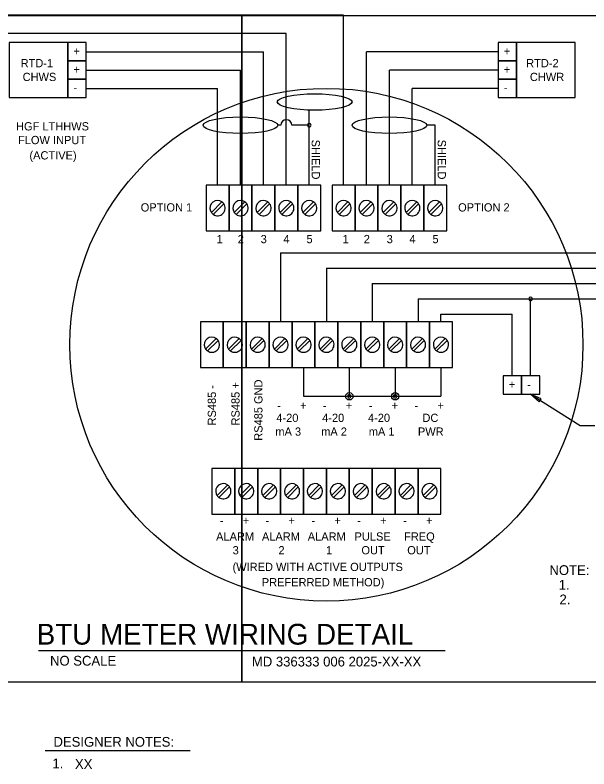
# Model space of a CAD drawing. Extents: x 10010.3 to 10109.1, y 10088 to 10139.5.
# Drawn here: x 10043.9 to 10083.1, y 10088 to 10139.5 of the extents above; entities that cross this region are included whole.
import ezdxf

# ---------------------------------------------------------------- set-up
doc = ezdxf.new("R2010")
doc.units = 0
for name, color, linetype in [('Default', 7, 'Continuous'), ('G-DETL-GRID', 7, 'Continuous'), ('G-DETL-LINE', 7, 'Continuous')]:
    doc.layers.add(name, color=color, linetype=linetype)

# ---------------------------------------------------------------- blocks, each defined once
blk = doc.blocks.new('leadarrow-a')
blk.add_lwpolyline([(0.00814, -0.00136), (0.00814, 0.00136), (0, 0)], close=True)

msp = doc.modelspace()

# ---------------------------------------------------------------- linework, layer by layer
for p, q in [((10079.106, 10113.625), (10082.496, 10111.49)), ((10082.496, 10111.49), (10083.487, 10111.49)), ((10045.538, 10096.133), (10073.277, 10096.133)), ((10046, 10089.309), (10055.886, 10089.309))]:
    msp.add_line(p, q)
at = {"layer": 'Default'}
for p, q in [((10058.055, 10126.754), (10057.331, 10126.029)), ((10057.46, 10125.9), (10058.184, 10126.625)), ((10059.618, 10126.754), (10058.893, 10126.029)), ((10059.022, 10125.9), (10059.747, 10126.625)), ((10061.18, 10126.754), (10060.456, 10126.029)), ((10060.585, 10125.9), (10061.309, 10126.625)), ((10062.743, 10126.754), (10062.018, 10126.029)), ((10062.147, 10125.9), (10062.872, 10126.625)), ((10064.305, 10126.754), (10063.581, 10126.029)), ((10063.71, 10125.9), (10064.434, 10126.625)), ((10066.649, 10126.754), (10065.925, 10126.029)), ((10066.053, 10125.9), (10066.778, 10126.625)), ((10068.212, 10126.754), (10067.487, 10126.029)), ((10067.616, 10125.9), (10068.341, 10126.625)), ((10069.774, 10126.754), (10069.05, 10126.029)), ((10069.178, 10125.9), (10069.903, 10126.625)), ((10071.337, 10126.754), (10070.612, 10126.029)), ((10070.741, 10125.9), (10071.466, 10126.625)), ((10072.899, 10126.754), (10072.175, 10126.029)), ((10072.303, 10125.9), (10073.028, 10126.625)), ((10079.106, 10114.875), (10079.106, 10120.126)), ((10072.992, 10118.563), (10072.992, 10119.078)), ((10072.992, 10119.078), (10077.856, 10119.078)), ((10077.856, 10114.875), (10077.856, 10119.078)), ((10057.665, 10117.427), (10056.94, 10116.702)), ((10057.069, 10116.574), (10057.794, 10117.298)), ((10059.227, 10117.427), (10058.503, 10116.702)), ((10058.632, 10116.574), (10059.356, 10117.298)), ((10060.79, 10117.427), (10060.065, 10116.702)), ((10060.194, 10116.574), (10060.919, 10117.298)), ((10062.352, 10117.427), (10061.628, 10116.702)), ((10061.757, 10116.574), (10062.481, 10117.298)), ((10063.915, 10117.427), (10063.19, 10116.702)), ((10063.319, 10116.574), (10064.044, 10117.298)), ((10065.477, 10117.427), (10064.753, 10116.702)), ((10064.882, 10116.574), (10065.606, 10117.298)), ((10067.04, 10117.427), (10066.315, 10116.702)), ((10066.444, 10116.574), (10067.169, 10117.298)), ((10068.602, 10117.427), (10067.878, 10116.702)), ((10068.007, 10116.574), (10068.731, 10117.298)), ((10070.165, 10117.427), (10069.44, 10116.702)), ((10069.569, 10116.574), (10070.294, 10117.298)), ((10071.727, 10117.427), (10071.003, 10116.702)), ((10071.132, 10116.574), (10071.856, 10117.298)), ((10073.29, 10117.427), (10072.565, 10116.702)), ((10072.694, 10116.574), (10073.419, 10117.298)), ((10063.617, 10115.438), (10063.617, 10113.481)), ((10066.742, 10115.438), (10066.742, 10113.481)), ((10069.867, 10115.438), (10069.867, 10113.481)), ((10072.992, 10115.438), (10072.992, 10113.481)), ((10063.617, 10113.481), (10066.742, 10113.481)), ((10066.742, 10113.481), (10069.867, 10113.481)), ((10069.867, 10113.481), (10072.992, 10113.481)), ((10058.446, 10107.427), (10057.722, 10106.702)), ((10057.85, 10106.574), (10058.575, 10107.298)), ((10060.009, 10107.427), (10059.284, 10106.702)), ((10059.413, 10106.574), (10060.137, 10107.298)), ((10061.571, 10107.427), (10060.847, 10106.702)), ((10060.975, 10106.574), (10061.7, 10107.298)), ((10063.134, 10107.427), (10062.409, 10106.702)), ((10062.538, 10106.574), (10063.262, 10107.298)), ((10064.696, 10107.427), (10063.972, 10106.702)), ((10064.1, 10106.574), (10064.825, 10107.298)), ((10066.259, 10107.427), (10065.534, 10106.702)), ((10065.663, 10106.574), (10066.387, 10107.298)), ((10067.821, 10107.427), (10067.097, 10106.702)), ((10067.225, 10106.574), (10067.95, 10107.298)), ((10069.384, 10107.427), (10068.659, 10106.702)), ((10068.788, 10106.574), (10069.512, 10107.298)), ((10070.946, 10107.427), (10070.222, 10106.702)), ((10070.35, 10106.574), (10071.075, 10107.298)), ((10072.509, 10107.427), (10071.784, 10106.702)), ((10071.913, 10106.574), (10072.637, 10107.298))]:
    msp.add_line(p, q, dxfattribs=at)
for points in [[(10056.976, 10124.765), (10058.539, 10124.765), (10058.539, 10127.89), (10056.976, 10127.89), (10056.976, 10124.765)], [(10058.539, 10124.765), (10060.101, 10124.765), (10060.101, 10127.89), (10058.539, 10127.89), (10058.539, 10124.765)], [(10060.101, 10124.765), (10061.664, 10124.765), (10061.664, 10127.89), (10060.101, 10127.89), (10060.101, 10124.765)], [(10061.664, 10124.765), (10063.226, 10124.765), (10063.226, 10127.89), (10061.664, 10127.89), (10061.664, 10124.765)], [(10063.226, 10124.765), (10064.789, 10124.765), (10064.789, 10127.89), (10063.226, 10127.89), (10063.226, 10124.765)], [(10065.57, 10124.765), (10067.133, 10124.765), (10067.133, 10127.89), (10065.57, 10127.89), (10065.57, 10124.765)], [(10067.133, 10124.765), (10068.695, 10124.765), (10068.695, 10127.89), (10067.133, 10127.89), (10067.133, 10124.765)], [(10068.695, 10124.765), (10070.258, 10124.765), (10070.258, 10127.89), (10068.695, 10127.89), (10068.695, 10124.765)], [(10070.258, 10124.765), (10071.82, 10124.765), (10071.82, 10127.89), (10070.258, 10127.89), (10070.258, 10124.765)], [(10071.82, 10124.765), (10073.383, 10124.765), (10073.383, 10127.89), (10071.82, 10127.89), (10071.82, 10124.765)], [(10056.586, 10115.438), (10058.148, 10115.438), (10058.148, 10118.563), (10056.586, 10118.563), (10056.586, 10115.438)], [(10058.148, 10115.438), (10059.711, 10115.438), (10059.711, 10118.563), (10058.148, 10118.563), (10058.148, 10115.438)], [(10059.711, 10115.438), (10061.273, 10115.438), (10061.273, 10118.563), (10059.711, 10118.563), (10059.711, 10115.438)], [(10061.273, 10115.438), (10062.836, 10115.438), (10062.836, 10118.563), (10061.273, 10118.563), (10061.273, 10115.438)], [(10062.836, 10115.438), (10064.398, 10115.438), (10064.398, 10118.563), (10062.836, 10118.563), (10062.836, 10115.438)], [(10064.398, 10115.438), (10065.961, 10115.438), (10065.961, 10118.563), (10064.398, 10118.563), (10064.398, 10115.438)], [(10065.961, 10115.438), (10067.523, 10115.438), (10067.523, 10118.563), (10065.961, 10118.563), (10065.961, 10115.438)], [(10067.523, 10115.438), (10069.086, 10115.438), (10069.086, 10118.563), (10067.523, 10118.563), (10067.523, 10115.438)], [(10069.086, 10115.438), (10070.648, 10115.438), (10070.648, 10118.563), (10069.086, 10118.563), (10069.086, 10115.438)], [(10070.648, 10115.438), (10072.211, 10115.438), (10072.211, 10118.563), (10070.648, 10118.563), (10070.648, 10115.438)], [(10072.211, 10115.438), (10073.773, 10115.438), (10073.773, 10118.563), (10072.211, 10118.563), (10072.211, 10115.438)], [(10077.231, 10113.625), (10078.481, 10113.625), (10078.481, 10114.875), (10077.231, 10114.875), (10077.231, 10113.625)], [(10078.481, 10113.625), (10079.731, 10113.625), (10079.731, 10114.875), (10078.481, 10114.875), (10078.481, 10113.625)], [(10057.367, 10105.438), (10058.929, 10105.438), (10058.929, 10108.563), (10057.367, 10108.563), (10057.367, 10105.438)], [(10058.929, 10105.438), (10060.492, 10105.438), (10060.492, 10108.563), (10058.929, 10108.563), (10058.929, 10105.438)], [(10060.492, 10105.438), (10062.054, 10105.438), (10062.054, 10108.563), (10060.492, 10108.563), (10060.492, 10105.438)], [(10062.054, 10105.438), (10063.617, 10105.438), (10063.617, 10108.563), (10062.054, 10108.563), (10062.054, 10105.438)], [(10063.617, 10105.438), (10065.179, 10105.438), (10065.179, 10108.563), (10063.617, 10108.563), (10063.617, 10105.438)], [(10065.179, 10105.438), (10066.742, 10105.438), (10066.742, 10108.563), (10065.179, 10108.563), (10065.179, 10105.438)], [(10066.742, 10105.438), (10068.304, 10105.438), (10068.304, 10108.563), (10066.742, 10108.563), (10066.742, 10105.438)], [(10068.304, 10105.438), (10069.867, 10105.438), (10069.867, 10108.563), (10068.304, 10108.563), (10068.304, 10105.438)], [(10069.867, 10105.438), (10071.429, 10105.438), (10071.429, 10108.563), (10069.867, 10108.563), (10069.867, 10105.438)], [(10071.429, 10105.438), (10072.992, 10105.438), (10072.992, 10108.563), (10071.429, 10108.563), (10071.429, 10105.438)]]:
    msp.add_lwpolyline(points, dxfattribs=at)
for centre, radius in [((10065.179, 10117), 17.5), ((10066.742, 10113.481), 0.25), ((10069.867, 10113.481), 0.25)]:
    msp.add_circle(centre, radius, dxfattribs=at)
for centre, radius, start, end in [((10057.758, 10126.327), 0.52, 55.0787, 200.4873), ((10059.32, 10126.327), 0.52, 55.0787, 200.4873), ((10060.883, 10126.327), 0.52, 55.0787, 200.4873), ((10062.445, 10126.327), 0.52, 55.0787, 200.4873), ((10064.008, 10126.327), 0.52, 55.0787, 200.4873), ((10066.351, 10126.327), 0.52, 55.0787, 200.4873), ((10067.914, 10126.327), 0.52, 55.0787, 200.4873), ((10069.476, 10126.327), 0.52, 55.0787, 200.4873), ((10071.039, 10126.327), 0.52, 55.0787, 200.4873), ((10072.601, 10126.327), 0.52, 55.0787, 200.4873), ((10057.758, 10126.327), 0.52, 235.0787, 34.9213), ((10057.758, 10126.327), 0.52, 34.9213, 55.0787), ((10059.32, 10126.327), 0.52, 235.0787, 34.9213), ((10059.32, 10126.327), 0.52, 34.9213, 55.0787), ((10060.883, 10126.327), 0.52, 235.0787, 34.9213), ((10060.883, 10126.327), 0.52, 34.9213, 55.0787), ((10062.445, 10126.327), 0.52, 235.0787, 34.9213), ((10062.445, 10126.327), 0.52, 34.9213, 55.0787), ((10064.008, 10126.327), 0.52, 235.0787, 34.9213), ((10064.008, 10126.327), 0.52, 34.9213, 55.0787), ((10066.351, 10126.327), 0.52, 235.0787, 34.9213), ((10066.351, 10126.327), 0.52, 34.9213, 55.0787), ((10067.914, 10126.327), 0.52, 235.0787, 34.9213), ((10067.914, 10126.327), 0.52, 34.9213, 55.0787), ((10069.476, 10126.327), 0.52, 235.0787, 34.9213), ((10069.476, 10126.327), 0.52, 34.9213, 55.0787), ((10071.039, 10126.327), 0.52, 235.0787, 34.9213), ((10071.039, 10126.327), 0.52, 34.9213, 55.0787), ((10072.601, 10126.327), 0.52, 235.0787, 34.9213), ((10072.601, 10126.327), 0.52, 34.9213, 55.0787), ((10057.758, 10126.327), 0.52, 200.4873, 214.9213), ((10057.758, 10126.327), 0.52, 214.9213, 235.0787), ((10059.32, 10126.327), 0.52, 200.4873, 214.9213), ((10059.32, 10126.327), 0.52, 214.9213, 235.0787), ((10060.883, 10126.327), 0.52, 200.4873, 214.9213), ((10060.883, 10126.327), 0.52, 214.9213, 235.0787), ((10062.445, 10126.327), 0.52, 200.4873, 214.9213), ((10062.445, 10126.327), 0.52, 214.9213, 235.0787), ((10064.008, 10126.327), 0.52, 200.4873, 214.9213), ((10064.008, 10126.327), 0.52, 214.9213, 235.0787), ((10066.351, 10126.327), 0.52, 200.4873, 214.9213), ((10066.351, 10126.327), 0.52, 214.9213, 235.0787), ((10067.914, 10126.327), 0.52, 200.4873, 214.9213), ((10067.914, 10126.327), 0.52, 214.9213, 235.0787), ((10069.476, 10126.327), 0.52, 200.4873, 214.9213), ((10069.476, 10126.327), 0.52, 214.9213, 235.0787), ((10071.039, 10126.327), 0.52, 200.4873, 214.9213), ((10071.039, 10126.327), 0.52, 214.9213, 235.0787), ((10072.601, 10126.327), 0.52, 200.4873, 214.9213), ((10072.601, 10126.327), 0.52, 214.9213, 235.0787), ((10079.106, 10120.126), 0.125, 0, 180), ((10079.106, 10120.126), 0.125, 180, 0), ((10057.367, 10117), 0.52, 55.0787, 200.4873), ((10057.367, 10117), 0.52, 235.0787, 34.9213), ((10057.367, 10117), 0.52, 34.9213, 55.0787), ((10058.929, 10117), 0.52, 55.0787, 200.4873), ((10058.929, 10117), 0.52, 235.0787, 34.9213), ((10058.929, 10117), 0.52, 34.9213, 55.0787), ((10060.492, 10117), 0.52, 55.0787, 200.4873), ((10060.492, 10117), 0.52, 235.0787, 34.9213), ((10060.492, 10117), 0.52, 34.9213, 55.0787), ((10062.054, 10117), 0.52, 55.0787, 200.4873), ((10062.054, 10117), 0.52, 235.0787, 34.9213), ((10062.054, 10117), 0.52, 34.9213, 55.0787), ((10063.617, 10117), 0.52, 55.0787, 200.4873), ((10063.617, 10117), 0.52, 235.0787, 34.9213), ((10063.617, 10117), 0.52, 34.9213, 55.0787), ((10065.179, 10117), 0.52, 55.0787, 200.4873), ((10065.179, 10117), 0.52, 235.0787, 34.9213), ((10065.179, 10117), 0.52, 34.9213, 55.0787), ((10066.742, 10117), 0.52, 55.0787, 200.4873), ((10066.742, 10117), 0.52, 235.0787, 34.9213), ((10066.742, 10117), 0.52, 34.9213, 55.0787), ((10068.304, 10117), 0.52, 55.0787, 200.4873), ((10068.304, 10117), 0.52, 235.0787, 34.9213), ((10068.304, 10117), 0.52, 34.9213, 55.0787), ((10069.867, 10117), 0.52, 55.0787, 200.4873), ((10069.867, 10117), 0.52, 235.0787, 34.9213), ((10069.867, 10117), 0.52, 34.9213, 55.0787), ((10071.429, 10117), 0.52, 55.0787, 200.4873), ((10071.429, 10117), 0.52, 235.0787, 34.9213), ((10071.429, 10117), 0.52, 34.9213, 55.0787), ((10072.992, 10117), 0.52, 55.0787, 200.4873), ((10072.992, 10117), 0.52, 235.0787, 34.9213), ((10072.992, 10117), 0.52, 34.9213, 55.0787), ((10057.367, 10117), 0.52, 200.4873, 214.9213), ((10057.367, 10117), 0.52, 214.9213, 235.0787), ((10058.929, 10117), 0.52, 200.4873, 214.9213), ((10058.929, 10117), 0.52, 214.9213, 235.0787), ((10060.492, 10117), 0.52, 200.4873, 214.9213), ((10060.492, 10117), 0.52, 214.9213, 235.0787), ((10062.054, 10117), 0.52, 200.4873, 214.9213), ((10062.054, 10117), 0.52, 214.9213, 235.0787), ((10063.617, 10117), 0.52, 200.4873, 214.9213), ((10063.617, 10117), 0.52, 214.9213, 235.0787), ((10065.179, 10117), 0.52, 200.4873, 214.9213), ((10065.179, 10117), 0.52, 214.9213, 235.0787), ((10066.742, 10117), 0.52, 200.4873, 214.9213), ((10066.742, 10117), 0.52, 214.9213, 235.0787), ((10068.304, 10117), 0.52, 200.4873, 214.9213), ((10068.304, 10117), 0.52, 214.9213, 235.0787), ((10069.867, 10117), 0.52, 200.4873, 214.9213), ((10069.867, 10117), 0.52, 214.9213, 235.0787), ((10071.429, 10117), 0.52, 200.4873, 214.9213), ((10071.429, 10117), 0.52, 214.9213, 235.0787), ((10072.992, 10117), 0.52, 200.4873, 214.9213), ((10072.992, 10117), 0.52, 214.9213, 235.0787), ((10066.742, 10113.481), 0.125, 0, 180), ((10066.742, 10113.481), 0.125, 180, 0), ((10069.867, 10113.481), 0.125, 0, 180), ((10069.867, 10113.481), 0.125, 180, 0), ((10058.148, 10107), 0.52, 55.0787, 200.4873), ((10058.148, 10107), 0.52, 235.0787, 34.9213), ((10058.148, 10107), 0.52, 34.9213, 55.0787), ((10059.711, 10107), 0.52, 55.0787, 200.4873), ((10059.711, 10107), 0.52, 235.0787, 34.9213), ((10059.711, 10107), 0.52, 34.9213, 55.0787), ((10061.273, 10107), 0.52, 55.0787, 200.4873), ((10061.273, 10107), 0.52, 235.0787, 34.9213), ((10061.273, 10107), 0.52, 34.9213, 55.0787), ((10062.836, 10107), 0.52, 55.0787, 200.4873), ((10062.836, 10107), 0.52, 235.0787, 34.9213), ((10062.836, 10107), 0.52, 34.9213, 55.0787), ((10064.398, 10107), 0.52, 55.0787, 200.4873), ((10064.398, 10107), 0.52, 235.0787, 34.9213), ((10064.398, 10107), 0.52, 34.9213, 55.0787), ((10065.961, 10107), 0.52, 55.0787, 200.4873), ((10065.961, 10107), 0.52, 235.0787, 34.9213), ((10065.961, 10107), 0.52, 34.9213, 55.0787), ((10067.523, 10107), 0.52, 55.0787, 200.4873), ((10067.523, 10107), 0.52, 235.0787, 34.9213), ((10067.523, 10107), 0.52, 34.9213, 55.0787), ((10069.086, 10107), 0.52, 55.0787, 200.4873), ((10069.086, 10107), 0.52, 235.0787, 34.9213), ((10069.086, 10107), 0.52, 34.9213, 55.0787), ((10070.648, 10107), 0.52, 55.0787, 200.4873), ((10070.648, 10107), 0.52, 235.0787, 34.9213), ((10070.648, 10107), 0.52, 34.9213, 55.0787), ((10072.211, 10107), 0.52, 55.0787, 200.4873), ((10072.211, 10107), 0.52, 235.0787, 34.9213), ((10072.211, 10107), 0.52, 34.9213, 55.0787), ((10058.148, 10107), 0.52, 200.4873, 214.9213), ((10059.711, 10107), 0.52, 200.4873, 214.9213), ((10061.273, 10107), 0.52, 200.4873, 214.9213), ((10062.836, 10107), 0.52, 200.4873, 214.9213), ((10064.398, 10107), 0.52, 200.4873, 214.9213), ((10065.961, 10107), 0.52, 200.4873, 214.9213), ((10067.523, 10107), 0.52, 200.4873, 214.9213), ((10069.086, 10107), 0.52, 200.4873, 214.9213), ((10070.648, 10107), 0.52, 200.4873, 214.9213), ((10072.211, 10107), 0.52, 200.4873, 214.9213), ((10058.148, 10107), 0.52, 214.9213, 235.0787), ((10059.711, 10107), 0.52, 214.9213, 235.0787), ((10061.273, 10107), 0.52, 214.9213, 235.0787), ((10062.836, 10107), 0.52, 214.9213, 235.0787), ((10064.398, 10107), 0.52, 214.9213, 235.0787), ((10065.961, 10107), 0.52, 214.9213, 235.0787), ((10067.523, 10107), 0.52, 214.9213, 235.0787), ((10069.086, 10107), 0.52, 214.9213, 235.0787), ((10070.648, 10107), 0.52, 214.9213, 235.0787), ((10072.211, 10107), 0.52, 214.9213, 235.0787)]:
    msp.add_arc(centre, radius, start, end, dxfattribs=at)
at = {"layer": 'G-DETL-GRID'}
for points in [[(10010.265, 10139.467), (10059.407, 10139.467), (10059.407, 10093.967), (10010.265, 10093.967)], [(10059.407, 10139.467), (10108.549, 10139.467), (10108.549, 10093.967), (10059.407, 10093.967)]]:
    msp.add_lwpolyline(points, close=True, dxfattribs=at)
at = {"layer": 'G-DETL-LINE'}
for p, q in [((10066.351, 10139.5), (10040.222, 10139.5)), ((10066.351, 10127.89), (10066.351, 10139.5)), ((10062.445, 10138.25), (10041.472, 10138.25)), ((10062.445, 10127.89), (10062.445, 10138.25)), ((10048.794, 10137), (10060.883, 10137)), ((10060.883, 10127.89), (10060.883, 10137)), ((10067.914, 10127.89), (10067.914, 10137)), ((10076.892, 10137), (10067.914, 10137)), ((10048.794, 10135.75), (10059.32, 10135.75)), ((10059.32, 10127.89), (10059.32, 10135.75)), ((10069.476, 10127.89), (10069.476, 10135.75)), ((10076.892, 10135.75), (10069.476, 10135.75)), ((10048.794, 10134.5), (10057.758, 10134.5)), ((10057.758, 10127.89), (10057.758, 10134.5)), ((10071.039, 10127.89), (10071.039, 10134.5)), ((10076.892, 10134.5), (10071.039, 10134.5)), ((10064.008, 10131.984), (10064.008, 10133.015)), ((10062.07, 10131.984), (10061.869, 10131.984)), ((10064.008, 10131.984), (10062.82, 10131.984)), ((10064.008, 10127.89), (10064.008, 10132.484)), ((10072.601, 10131.984), (10072.025, 10131.984)), ((10072.601, 10127.89), (10072.601, 10131.984)), ((10062.054, 10123.27), (10089.512, 10123.27)), ((10062.054, 10123.27), (10062.054, 10118.563)), ((10065.179, 10122.222), (10094.867, 10122.222)), ((10065.179, 10122.222), (10065.179, 10118.563)), ((10068.304, 10121.174), (10100.429, 10121.174)), ((10068.304, 10121.174), (10068.304, 10118.563)), ((10071.429, 10120.126), (10101.679, 10120.126)), ((10071.429, 10120.126), (10071.429, 10118.563))]:
    msp.add_line(p, q, dxfattribs=at)
for points in [[(10047.544, 10137.625), (10043.544, 10137.625), (10043.544, 10133.875), (10047.544, 10133.875), (10047.544, 10137.625)], [(10047.544, 10136.375), (10048.794, 10136.375), (10048.794, 10137.625), (10047.544, 10137.625), (10047.544, 10136.375)], [(10076.892, 10136.375), (10078.142, 10136.375), (10078.142, 10137.625), (10076.892, 10137.625), (10076.892, 10136.375)], [(10082.142, 10137.625), (10078.142, 10137.625), (10078.142, 10133.875), (10082.142, 10133.875), (10082.142, 10137.625)], [(10047.544, 10135.125), (10048.794, 10135.125), (10048.794, 10136.375), (10047.544, 10136.375), (10047.544, 10135.125)], [(10076.892, 10135.125), (10078.142, 10135.125), (10078.142, 10136.375), (10076.892, 10136.375), (10076.892, 10135.125)], [(10047.544, 10133.875), (10048.794, 10133.875), (10048.794, 10135.125), (10047.544, 10135.125), (10047.544, 10133.875)], [(10076.892, 10133.875), (10078.142, 10133.875), (10078.142, 10135.125), (10076.892, 10135.125), (10076.892, 10133.875)]]:
    msp.add_lwpolyline(points, dxfattribs=at)
for centre, radius, start, end in [((10062.445, 10131.984), 0.375, 0, 180), ((10064.008, 10131.984), 0.125, 0, 180), ((10064.008, 10131.984), 0.125, 180, 0)]:
    msp.add_arc(centre, radius, start, end, dxfattribs=at)
for centre in [(10064.377, 10133.57), (10059.32, 10131.984), (10069.476, 10131.984)]:
    msp.add_ellipse(centre, major_axis=(-2.549, 0), ratio=0.219876, dxfattribs=at)

# ---------------------------------------------------------------- block references
at = {"xscale": 96, "yscale": 96, "rotation": -32.29415711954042}
msp.add_blockref('leadarrow-a', (10079.106, 10113.625), dxfattribs=at)

# ---------------------------------------------------------------- texts
for s, height, p in [('BTU METER WIRING DETAIL', 1.41667, (10045.422, 10096.534)), ('NO SCALE', 0.6667, (10046.331, 10095.098))]:
    msp.add_text(s, height=height).set_placement(p)
at = {"layer": 'Default'}
for s, height, p in [('HGF LTHHWS', 0.5625, (10044.014, 10131.627)), ('FLOW INPUT', 0.5625, (10044.148, 10130.69)), ('(ACTIVE)', 0.5625, (10044.925, 10129.645)), ('OPTION 1', 0.5625, (10052.515, 10126.094)), ('OPTION 2', 0.5625, (10074.164, 10126.094)), ('1', 0.563, (10057.691, 10123.931)), ('2', 0.563, (10059.133, 10123.931)), ('3', 0.563, (10060.695, 10123.931)), ('4', 0.563, (10062.244, 10123.931)), ('5', 0.563, (10063.82, 10123.931)), ('1', 0.563, (10066.284, 10123.931)), ('2', 0.563, (10067.726, 10123.931)), ('3', 0.563, (10069.289, 10123.931)), ('4', 0.563, (10070.838, 10123.931)), ('5', 0.563, (10072.414, 10123.931)), ('+', 0.563, (10077.615, 10114.009)), ('-', 0.563, (10078.865, 10114.009)), ('+', 0.563, (10063.376, 10112.571)), ('+', 0.563, (10066.501, 10112.571)), ('+', 0.563, (10069.626, 10112.571)), ('+', 0.563, (10072.751, 10112.571)), ('-', 0.563, (10061.813, 10112.571)), ('-', 0.563, (10064.938, 10112.571)), ('-', 0.563, (10068.063, 10112.571)), ('-', 0.563, (10071.188, 10112.571)), ('4-20 ', 0.5625, (10061.764, 10111.729)), ('4-20 ', 0.5625, (10064.889, 10111.729)), ('4-20 ', 0.5625, (10068.014, 10111.729)), ('DC ', 0.5625, (10071.729, 10111.729)), ('mA 3', 0.5625, (10061.697, 10110.791)), ('mA 2', 0.5625, (10064.822, 10110.791)), ('mA 1', 0.5625, (10068.068, 10110.791)), ('PWR', 0.5625, (10071.421, 10110.791)), ('-', 0.563, (10057.907, 10104.718)), ('+', 0.563, (10059.47, 10104.718)), ('-', 0.563, (10061.032, 10104.718)), ('+', 0.563, (10062.595, 10104.718)), ('-', 0.563, (10064.157, 10104.718)), ('+', 0.563, (10065.72, 10104.718)), ('-', 0.563, (10067.282, 10104.718)), ('+', 0.563, (10068.845, 10104.718)), ('-', 0.563, (10070.407, 10104.718)), ('+', 0.563, (10071.97, 10104.718)), ('PULSE ', 0.5625, (10067.099, 10103.631)), ('FREQ ', 0.5625, (10070.478, 10103.631)), ('ALARM ', 0.5625, (10057.657, 10103.631)), ('ALARM ', 0.5625, (10060.782, 10103.631)), ('ALARM ', 0.5625, (10063.907, 10103.631)), ('3', 0.563, (10058.782, 10102.694)), ('2', 0.563, (10061.907, 10102.694)), ('1', 0.563, (10065.152, 10102.694)), ('OUT', 0.5625, (10067.567, 10102.694)), ('OUT', 0.5625, (10070.692, 10102.694)), ('(WIRED WITH ACTIVE OUTPUTS', 0.5625, (10058.777, 10101.555)), ('PREFERRED METHOD)', 0.5625, (10060.773, 10100.511))]:
    msp.add_text(s, height=height, dxfattribs=at).set_placement(p)
for s, rotation, p in [('SHIELD', 270, (10064.175, 10130.997)), ('SHIELD', 270, (10072.769, 10130.997)), ('RS485 GND', 90, (10060.82, 10110.447)), ('RS485 -', 90, (10057.648, 10111.491)), ('RS485 +', 90, (10059.258, 10111.491))]:
    msp.add_text(s, height=0.5625, rotation=rotation, dxfattribs=at).set_placement(p)
at = {"layer": 'G-DETL-LINE'}
for s, height, p in [('+', 0.563, (10047.928, 10136.759)), ('+', 0.563, (10077.276, 10136.759)), ('RTD-1', 0.5625, (10044.326, 10135.938)), ('RTD-2', 0.5625, (10078.803, 10135.938)), ('+', 0.563, (10047.928, 10135.509)), ('+', 0.563, (10077.276, 10135.509)), ('CHWS', 0.5625, (10044.46, 10135)), ('CHWR', 0.5625, (10079.057, 10135)), ('-', 0.563, (10047.928, 10134.259)), ('-', 0.563, (10077.276, 10134.259)), ('NOTE:', 0.6667, (10080.391, 10101.283)), ('1.', 0.6667, (10081.024, 10100.283)), ('2.', 0.6667, (10081.077, 10099.283)), ('MD 336333 006 2025-XX-XX', 0.66667, (10060.099, 10095.04)), ('DESIGNER NOTES:', 0.66667, (10046.566, 10089.563)), ('1.', 0.6667, (10046.493, 10088.092)), ('XX', 0.6667, (10048.031, 10088.048))]:
    msp.add_text(s, height=height, dxfattribs=at).set_placement(p)

doc.saveas('drawing.dxf')
